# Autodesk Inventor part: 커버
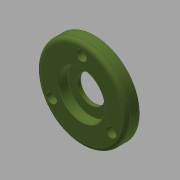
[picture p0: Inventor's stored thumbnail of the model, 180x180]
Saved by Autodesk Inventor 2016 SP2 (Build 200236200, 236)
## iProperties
Created: 2016-06
Part Number: 커버
Material: 알루미늄 6061
Document SubType Name: Modeling
Designer: mduedu
Density: 2.71 g/cm^3
Appearance: 올리브 녹색
Author: mduedu
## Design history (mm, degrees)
sketch "스케치1"
  geometry: C1 r 34 at (0, 0); 1 further point
  constraints: 1 centre point, 1 coincident
  dimensions: "d0" = 68 diameter of C1
extrude "돌출1" new body sketch "스케치1" distance "d2" = 10; taper "d3" = 0 deg
sketch "스케치2"
  geometry: C1 r 21 at (0, 0); 1 further point
  constraints: 1 centre point, 1 coincident
  dimensions: "d4" = 42 diameter of C1
extrude "돌출2" join sketch "스케치2" distance "d6" = 3; taper "d7" = 0 deg
fillet "모깎기1" dims "d8" = 3
hole "구멍1" diameter "d11" = 35; stored, may be unused: countersink angle "d15" = 90 deg, drill point angle "d17" = 0 deg; dims "d9" = 10, "d10" = 10, "d12" = 6, "d13" = 4, "d14" = 2, "d16" = 3
hole "구멍2" diameter "d20" = 35; stored, may be unused: countersink angle "d24" = 90 deg, drill point angle "d26" = 0 deg; dims "d21" = 6, "d22" = 4, "d23" = 2, "d25" = 7.3, "d73" = 10, "d74" = 10
hole "구멍3" diameter "d29" = 21; stored, may be unused: countersink angle "d33" = 90 deg, drill point angle "d35" = 0 deg; dims "d27" = 10, "d28" = 10, "d30" = 6, "d31" = 4, "d32" = 2, "d34" = 5
fillet "모깎기2" dims "d36" = 3
fillet "모깎기3" dims "d37" = 0.1
chamfer "모따기1" distance "d38" = 0.7; stored, may be unused: second distance "d39" = 2, angle "d40" = 30 deg
chamfer "모따기2" distance "d42" = 0.5; stored, may be unused: second distance "d43" = 2, angle "d44" = 30 deg
sketch "스케치5" dims "d60" = 52
  geometry: 3 further points
  constraints: 2 vertical alignment, 1 coincident, 2 other
hole "구멍5" sketch "스케치5" at (0, 26) diameter "d61" = 4.5; stored, may be unused: countersink angle "d65" = 90 deg, drill point angle "d67" = 118 deg; dims "d62" = 6, "d63" = 8, "d64" = 4.6, "d66" = 8
node "솔리드1"
pattern_circular "원형 패턴1" dims angle "d69" = 360 deg
